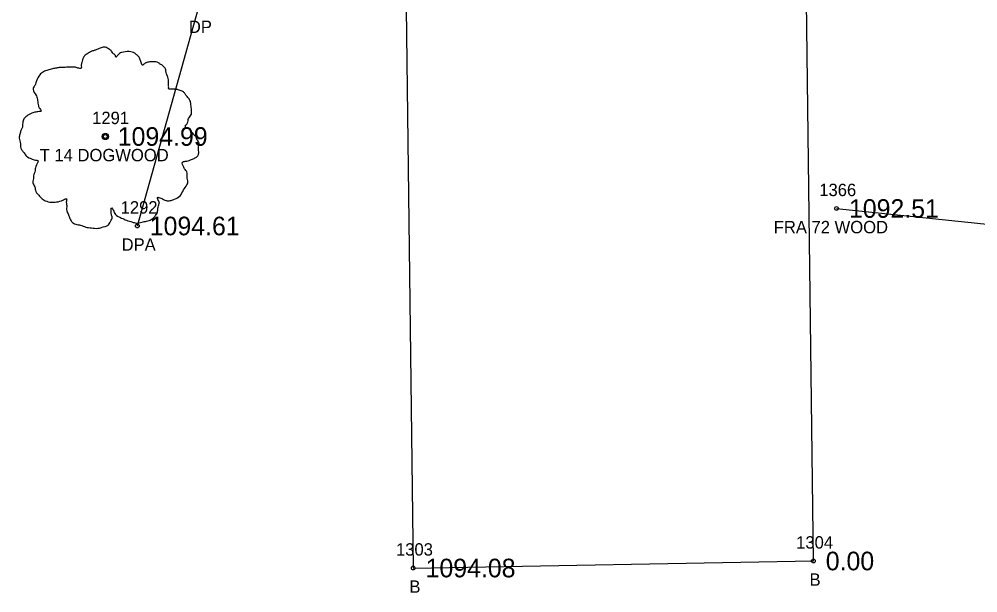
# Model space of a CAD drawing. Extents: x 1539151 to 1541799, y 1198646 to 1201165.
# Drawn here: x 1539645.8 to 1539723.1, y 1199245.3 to 1199291.6 of the extents above; entities that cross this region are included whole.
import ezdxf

# ---------------------------------------------------------------- set-up
doc = ezdxf.new("R2010")
doc.units = 0
for name, color, linetype in [('RD_EX_Bldg', 7, 'Continuous'), ('RD_EX_Bldg_txCode', 7, 'Continuous'), ('RD_EX_Driveway', 7, 'Continuous'), ('RD_EX_Driveway_txCode', 7, 'Continuous'), ('RD_EX_Fence_Other', 7, 'Continuous'), ('RD_EX_Fence_Other_txCode', 7, 'Continuous'), ('RD_EX_TX_Bldg_ELEV', 7, 'Continuous'), ('RD_EX_TX_Driveway_ELEV', 7, 'Continuous'), ('RD_EX_TX_Fence_Other_ELEV', 7, 'Continuous'), ('RD_EX_TX_VEG_ELEV', 7, 'Continuous'), ('RD_EX_VEG', 7, 'Continuous'), ('RD_EX_VEG_txCode', 7, 'Continuous'), ('RD_SMD_Locator', 7, 'Continuous')]:
    doc.layers.add(name, color=color, linetype=linetype)

msp = doc.modelspace()

# ---------------------------------------------------------------- linework, layer by layer
at = {"layer": 'RD_EX_Bldg'}
msp.add_lwpolyline([(1539709.303, 1199295.151), (1539677.036, 1199294.584), (1539677.619, 1199247.302), (1539709.886, 1199247.869), (1539709.303, 1199295.151)], dxfattribs=at)
at = {"layer": 'RD_EX_Driveway'}
msp.add_lwpolyline([(1539655.375, 1199274.883), (1539660.31, 1199292.444), (1539659.521, 1199341.436), (1539659.058, 1199347.097), (1539654.304, 1199353.638)], dxfattribs=at)
at = {"layer": 'RD_EX_Fence_Other'}
msp.add_line((1539711.757, 1199276.292), (1539768.917, 1199270.335), dxfattribs=at)
at = {"layer": 'RD_EX_VEG'}
for centre, radius in [((1539652.794, 1199282.098), 0.25), ((1539652.781, 1199282.08), 0.0001)]:
    msp.add_circle(centre, radius, dxfattribs=at)
for points in [[(1539652.926, 1199289.266), (1539652.626, 1199289.291), (1539652.301, 1199289.191), (1539652.051, 1199289.091), (1539651.826, 1199289.016), (1539651.601, 1199288.916), (1539651.301, 1199288.741), (1539651.076, 1199288.541), (1539650.951, 1199288.291), (1539650.901, 1199288.066), (1539650.851, 1199287.791), (1539650.851, 1199287.616), (1539650.727, 1199287.591), (1539650.577, 1199287.616), (1539650.327, 1199287.691), (1539650.077, 1199287.691), (1539649.827, 1199287.691), (1539649.477, 1199287.666), (1539649.127, 1199287.666), (1539648.852, 1199287.616), (1539648.527, 1199287.566), (1539648.153, 1199287.441), (1539647.803, 1199287.316), (1539647.503, 1199287.067), (1539647.253, 1199286.592), (1539647.128, 1199286.242), (1539646.978, 1199285.992), (1539647.128, 1199285.542), (1539647.303, 1199285.192), (1539647.328, 1199284.992), (1539647.403, 1199284.568), (1539647.503, 1199284.343), (1539647.628, 1199284.143), (1539647.553, 1199284.118), (1539647.178, 1199284.068), (1539646.878, 1199283.968), (1539646.453, 1199283.743), (1539646.228, 1199283.518), (1539646.128, 1199283.193), (1539646.104, 1199282.843), (1539646.004, 1199282.644), (1539645.929, 1199282.369), (1539645.904, 1199282.294), (1539645.854, 1199281.969), (1539645.954, 1199281.519), (1539645.979, 1199281.169), (1539646.104, 1199280.944), (1539646.253, 1199280.769), (1539646.428, 1199280.519), (1539646.828, 1199280.295), (1539647.153, 1199280.195), (1539647.353, 1199280.17), (1539647.178, 1199279.67), (1539647.128, 1199279.32), (1539647.003, 1199278.92), (1539647.003, 1199278.845), (1539646.953, 1199278.37), (1539647.103, 1199278.045), (1539647.178, 1199277.671), (1539647.353, 1199277.446), (1539647.628, 1199277.146), (1539647.953, 1199276.921), (1539648.453, 1199276.796), (1539648.852, 1199276.821), (1539649.427, 1199276.996), (1539649.677, 1199277.071), (1539649.652, 1199276.896), (1539649.677, 1199276.521), (1539649.677, 1199276.096), (1539649.827, 1199275.772), (1539649.927, 1199275.497), (1539650.077, 1199275.247), (1539650.402, 1199275.022), (1539650.801, 1199274.947), (1539651.226, 1199274.797), (1539651.676, 1199274.722), (1539652.176, 1199274.697), (1539652.776, 1199274.847), (1539653.05, 1199274.972), (1539653.15, 1199275.147), (1539653.35, 1199275.522), (1539653.3, 1199275.747), (1539653.325, 1199276.346), (1539653.425, 1199276.171), (1539653.6, 1199275.821), (1539654.1, 1199275.522), (1539654.5, 1199275.347), (1539654.975, 1199275.197), (1539655.275, 1199275.122), (1539655.749, 1199275.197), (1539656.124, 1199275.272), (1539656.499, 1199275.397), (1539656.799, 1199275.672), (1539656.974, 1199275.946), (1539657.024, 1199276.221), (1539657.099, 1199276.596), (1539657.149, 1199276.771)], [(1539657.149, 1199276.771), (1539657.074, 1199276.946), (1539657.024, 1199277.196), (1539657.099, 1199277.171), (1539657.274, 1199277.121), (1539657.549, 1199276.996), (1539657.773, 1199276.921), (1539658.098, 1199276.946), (1539658.373, 1199277.046), (1539658.823, 1199277.321), (1539659.098, 1199277.796), (1539659.373, 1199278.195), (1539659.448, 1199278.52), (1539659.398, 1199278.745), (1539659.373, 1199279.245), (1539659.173, 1199279.495), (1539659.123, 1199279.62), (1539659.023, 1199280.02), (1539659.098, 1199280.07), (1539659.373, 1199280.12), (1539659.748, 1199280.245), (1539660.022, 1199280.369), (1539660.247, 1199280.544), (1539660.322, 1199280.769), (1539660.297, 1199281.169), (1539660.347, 1199281.569), (1539660.272, 1199281.719), (1539660.172, 1199281.869), (1539660.097, 1199282.069), (1539659.947, 1199282.219), (1539659.848, 1199282.369), (1539659.748, 1199282.469), (1539659.623, 1199282.619), (1539659.448, 1199282.743), (1539659.298, 1199282.793), (1539659.248, 1199282.943), (1539659.398, 1199283.143), (1539659.448, 1199283.243), (1539659.473, 1199283.468), (1539659.698, 1199283.818), (1539659.748, 1199284.218), (1539659.698, 1199284.643), (1539659.648, 1199284.918), (1539659.498, 1199285.192), (1539659.298, 1199285.442), (1539659.173, 1199285.617), (1539658.998, 1199285.742), (1539658.673, 1199285.867), (1539658.423, 1199285.917), (1539658.073, 1199285.917), (1539657.873, 1199285.967), (1539657.898, 1199286.017), (1539657.898, 1199286.167), (1539657.898, 1199286.442), (1539657.823, 1199286.892), (1539657.673, 1199287.391), (1539657.673, 1199287.416), (1539657.573, 1199287.666), (1539657.349, 1199287.866), (1539657.174, 1199287.966), (1539656.974, 1199288.091), (1539656.724, 1199288.116), (1539656.424, 1199288.116), (1539656.149, 1199288.066), (1539655.949, 1199287.966), (1539655.774, 1199287.841), (1539655.699, 1199287.991), (1539655.599, 1199288.291), (1539655.549, 1199288.441), (1539655.399, 1199288.616), (1539655.175, 1199288.816), (1539654.725, 1199288.941), (1539654.1, 1199288.866), (1539653.8, 1199288.666), (1539653.65, 1199288.491), (1539653.6, 1199288.616), (1539653.4, 1199288.816), (1539653.3, 1199288.991), (1539653.125, 1199289.116), (1539652.976, 1199289.216), (1539652.876, 1199289.266)]]:
    msp.add_spline(points, degree=3, dxfattribs=at)
at = {"layer": 'RD_SMD_Locator'}
for centre in [(1539652.794, 1199282.098), (1539711.757, 1199276.292), (1539655.375, 1199274.883), (1539709.886, 1199247.869), (1539677.619, 1199247.302)]:
    msp.add_circle(centre, 0.15, dxfattribs=at)

# ---------------------------------------------------------------- texts
at = {"layer": 'RD_EX_Bldg_txCode'}
for s, p in [('1303', (1539676.233, 1199248.302)), ('1304', (1539708.5, 1199248.869)), ('B', (1539677.312, 1199245.302)), ('B', (1539709.579, 1199245.869))]:
    msp.add_text(s, height=1, dxfattribs=at).set_placement(p)
at = {"layer": 'RD_EX_Driveway_txCode'}
for s, p in [('DP', (1539659.53, 1199290.444)), ('1292', (1539654.029, 1199275.883)), ('DPA', (1539654.107, 1199272.883))]:
    msp.add_text(s, height=1, dxfattribs=at).set_placement(p)
at = {"layer": 'RD_EX_Fence_Other_txCode'}
for s, p in [('1366', (1539710.363, 1199277.292)), ('FRA 72 WOOD', (1539706.694, 1199274.292))]:
    msp.add_text(s, height=1, dxfattribs=at).set_placement(p)
at = {"layer": 'RD_EX_TX_Bldg_ELEV'}
for s, p in [('0.00', (1539710.886, 1199247.119)), ('1094.08', (1539678.619, 1199246.552))]:
    msp.add_text(s, height=1.5, dxfattribs=at).set_placement(p)
at = {"layer": 'RD_EX_TX_Driveway_ELEV'}
msp.add_text('1094.61', height=1.5, dxfattribs=at).set_placement((1539656.375, 1199274.133))
at = {"layer": 'RD_EX_TX_Fence_Other_ELEV'}
msp.add_text('1092.51', height=1.5, dxfattribs=at).set_placement((1539712.757, 1199275.542))
at = {"layer": 'RD_EX_TX_VEG_ELEV'}
msp.add_text('1094.99', height=1.5, dxfattribs=at).set_placement((1539653.794, 1199281.348))
at = {"layer": 'RD_EX_VEG_txCode'}
for s, p in [('1291', (1539651.731, 1199283.098)), ('T 14 DOGWOOD', (1539647.502, 1199280.098))]:
    msp.add_text(s, height=1, dxfattribs=at).set_placement(p)

doc.saveas('drawing.dxf')
